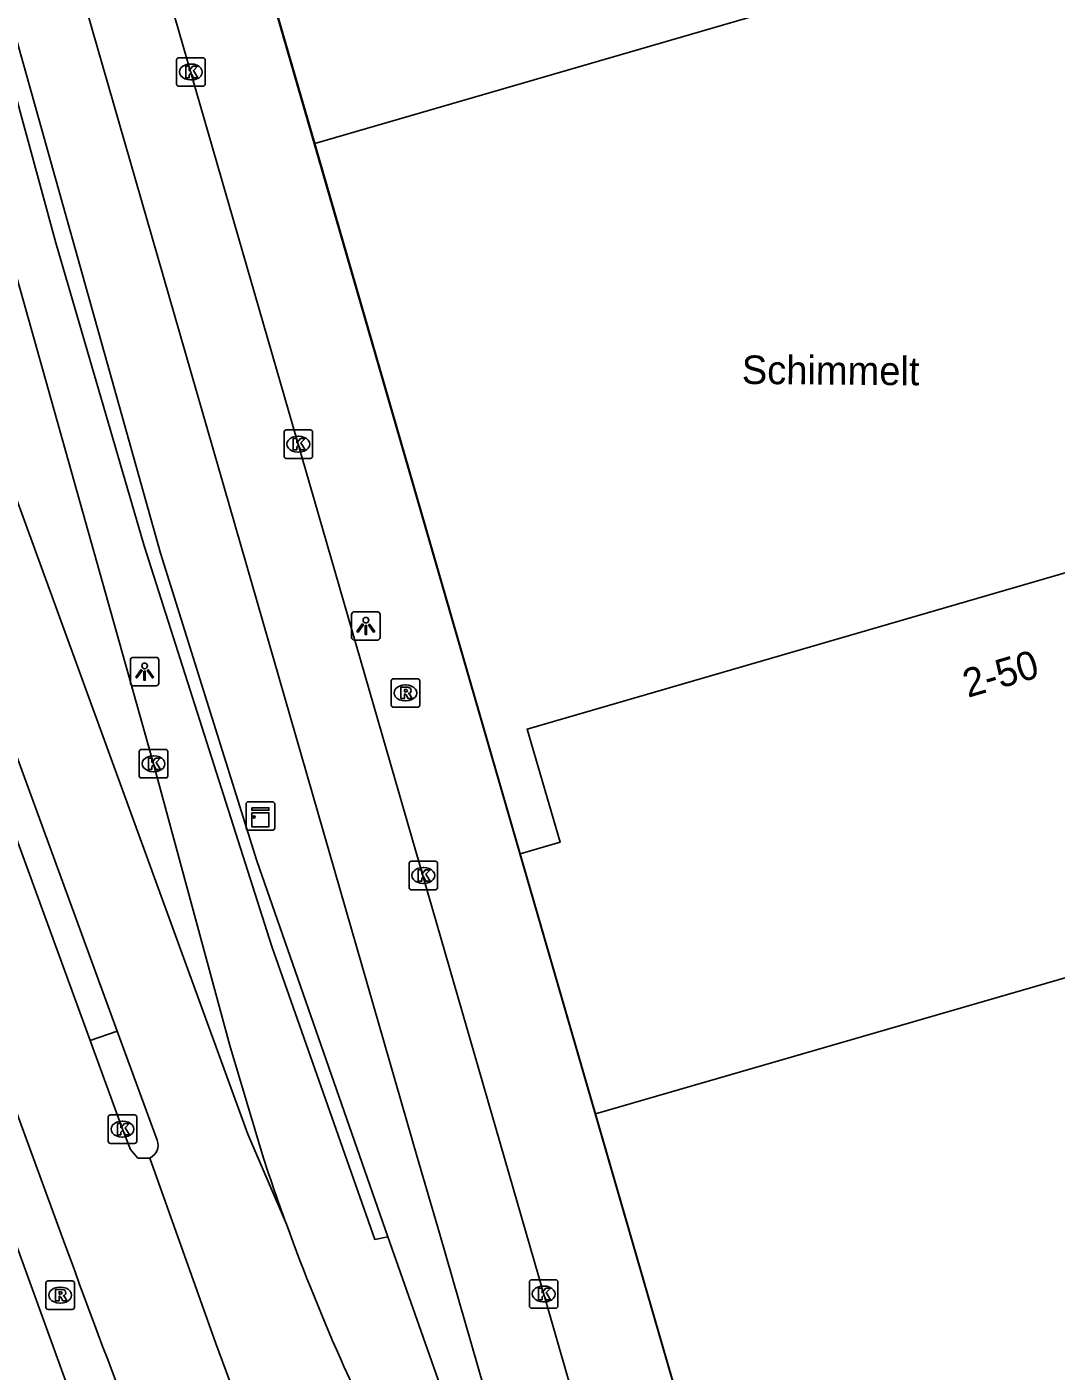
# Model space of a CAD drawing. Extents: x 160806 to 161707, y 383697 to 384148.
# Drawn here: x 161093.93 to 161130.08, y 383742.52 to 383789.72 of the extents above; entities that cross this region are included whole.
import ezdxf

# ---------------------------------------------------------------- set-up
doc = ezdxf.new("R2010")
doc.units = 0
for name, color, linetype in [('IMGEO_Fietspad_open', 7, 'Continuous'), ('IMGEO_Kast', 7, 'Continuous'), ('IMGEO_Kolk', 7, 'Continuous'), ('IMGEO_Lichtpunt', 7, 'Continuous'), ('IMGEO_Muur', 7, 'Continuous'), ('IMGEO_Openbare_ruimte_label', 7, 'Continuous'), ('IMGEO_OVBaan_gesloten', 7, 'Continuous'), ('IMGEO_Pand', 7, 'Continuous'), ('IMGEO_Pand_nummerreeks', 7, 'Continuous'), ('IMGEO_Pand_overbouw', 7, 'Continuous'), ('IMGEO_Rijbaan_lokaal_gesloten', 7, 'Continuous'), ('IMGEO_Rioolput', 7, 'Continuous'), ('IMGEO_Verkeerseiland_open', 7, 'Continuous'), ('IMGEO_Voetpad_open', 7, 'Continuous')]:
    doc.layers.add(name, color=color, linetype=linetype)

msp = doc.modelspace()

# ---------------------------------------------------------------- linework, layer by layer
at = {"layer": 'IMGEO_Fietspad_open'}
for points in [[(161122.975, 383708.589), (161122.859, 383708.842), (161122.656, 383709.073), (161122.247, 383709.896), (161112.327, 383744.363), (161110.707, 383750), (161094.816, 383804.968)], [(161092.305, 383803.171), (161107.65, 383750), (161108.414, 383747.365), (161112.465, 383733.297)]]:
    msp.add_lwpolyline(points, dxfattribs=at)
at = {"layer": 'IMGEO_Kast'}
for p, q in [((161101.63, 383761.583), (161101.63, 383762.424)), ((161101.63, 383762.424), (161101.63, 383761.583)), ((161101.705, 383762.508), (161102.546, 383762.508)), ((161102.546, 383762.508), (161101.705, 383762.508)), ((161102.63, 383762.433), (161102.63, 383761.592)), ((161102.63, 383761.592), (161102.63, 383762.433)), ((161102.555, 383761.508), (161101.714, 383761.508)), ((161101.714, 383761.508), (161102.555, 383761.508))]:
    msp.add_line(p, q, dxfattribs=at)
for points in [[(161101.825, 383762.298), (161102.425, 383762.298), (161102.425, 383762.213), (161101.825, 383762.213), (161101.825, 383762.298)], [(161101.825, 383762.123), (161102.425, 383762.123), (161102.425, 383761.634), (161101.825, 383761.634), (161101.825, 383762.123)]]:
    msp.add_lwpolyline(points, dxfattribs=at)
msp.add_circle((161101.909, 383761.972), 0.0377, dxfattribs=at)
for centre, start, end in [((161101.708, 383762.43), 92.4484, 184.2845), ((161101.708, 383762.43), 92.4484, 184.2845), ((161102.552, 383762.43), 2.4484, 94.2845), ((161102.552, 383762.43), 2.4484, 94.2845), ((161101.708, 383761.586), 182.4484, 274.2845), ((161101.708, 383761.586), 182.4484, 274.2845), ((161102.552, 383761.586), 272.4484, 4.2845), ((161102.552, 383761.586), 272.4484, 4.2845)]:
    msp.add_arc(centre, 0.0779, start, end, dxfattribs=at)
at = {"layer": 'IMGEO_Kolk'}
for p, q in [((161099.186, 383787.707), (161099.186, 383788.559)), ((161099.261, 383788.633), (161100.113, 383788.633)), ((161100.187, 383788.559), (161100.187, 383787.707)), ((161099.674, 383788.413), (161099.699, 383788.413)), ((161100.113, 383787.633), (161099.261, 383787.633)), ((161099.697, 383787.853), (161099.672, 383787.853)), ((161102.959, 383774.637), (161102.959, 383775.489)), ((161103.034, 383775.563), (161103.886, 383775.563)), ((161103.447, 383775.343), (161103.472, 383775.343)), ((161103.96, 383775.489), (161103.96, 383774.637)), ((161103.47, 383774.783), (161103.445, 383774.783)), ((161103.886, 383774.563), (161103.034, 383774.563)), ((161097.874, 383763.418), (161097.874, 383764.27)), ((161097.949, 383764.344), (161098.801, 383764.344)), ((161098.362, 383764.124), (161098.387, 383764.124)), ((161098.875, 383764.27), (161098.875, 383763.418)), ((161098.385, 383763.564), (161098.36, 383763.564)), ((161098.801, 383763.344), (161097.949, 383763.344)), ((161107.351, 383759.496), (161107.351, 383760.348)), ((161107.426, 383760.422), (161108.278, 383760.422)), ((161107.839, 383760.202), (161107.864, 383760.202)), ((161108.352, 383760.348), (161108.352, 383759.496)), ((161108.278, 383759.422), (161107.426, 383759.422)), ((161107.862, 383759.642), (161107.837, 383759.642)), ((161096.783, 383750.588), (161096.783, 383751.44)), ((161096.858, 383751.514), (161097.71, 383751.514)), ((161097.271, 383751.294), (161097.296, 383751.294)), ((161097.784, 383751.44), (161097.784, 383750.588)), ((161097.294, 383750.734), (161097.269, 383750.734)), ((161097.71, 383750.514), (161096.858, 383750.514)), ((161111.578, 383744.799), (161111.578, 383745.651)), ((161111.653, 383745.725), (161112.505, 383745.725)), ((161112.579, 383745.651), (161112.579, 383744.799)), ((161112.066, 383745.505), (161112.091, 383745.505)), ((161112.505, 383744.725), (161111.653, 383744.725)), ((161112.089, 383744.945), (161112.064, 383744.945))]:
    msp.add_line(p, q, dxfattribs=at)
for points in [[(161099.186, 383787.707), (161099.186, 383788.559)], [(161099.261, 383788.633), (161100.113, 383788.633)], [(161100.187, 383788.559), (161100.187, 383787.707)], [(161099.507, 383788.333), (161099.63, 383788.333), (161099.63, 383788.182), (161099.76, 383788.333), (161099.924, 383788.333), (161099.778, 383788.182), (161099.931, 383787.933), (161099.779, 383787.933), (161099.694, 383788.097), (161099.63, 383788.03), (161099.63, 383787.933), (161099.507, 383787.933), (161099.507, 383788.333)], [(161100.113, 383787.633), (161099.261, 383787.633)], [(161102.959, 383774.637), (161102.959, 383775.489)], [(161103.034, 383775.563), (161103.886, 383775.563)], [(161103.28, 383775.263), (161103.403, 383775.263), (161103.403, 383775.112), (161103.533, 383775.263), (161103.697, 383775.263), (161103.551, 383775.112), (161103.704, 383774.863), (161103.552, 383774.863), (161103.467, 383775.027), (161103.403, 383774.96), (161103.403, 383774.863), (161103.28, 383774.863), (161103.28, 383775.263)], [(161103.96, 383775.489), (161103.96, 383774.637)], [(161103.886, 383774.563), (161103.034, 383774.563)], [(161097.874, 383763.418), (161097.874, 383764.27)], [(161097.949, 383764.344), (161098.801, 383764.344)], [(161098.195, 383764.044), (161098.318, 383764.044), (161098.318, 383763.893), (161098.448, 383764.044), (161098.612, 383764.044), (161098.466, 383763.893), (161098.619, 383763.644), (161098.467, 383763.644), (161098.382, 383763.808), (161098.318, 383763.741), (161098.318, 383763.644), (161098.195, 383763.644), (161098.195, 383764.044)], [(161098.875, 383764.27), (161098.875, 383763.418)], [(161098.801, 383763.344), (161097.949, 383763.344)], [(161107.351, 383759.496), (161107.351, 383760.348)], [(161107.426, 383760.422), (161108.278, 383760.422)], [(161108.352, 383760.348), (161108.352, 383759.496)], [(161107.672, 383760.122), (161107.795, 383760.122), (161107.795, 383759.971), (161107.925, 383760.122), (161108.089, 383760.122), (161107.943, 383759.971), (161108.096, 383759.722), (161107.944, 383759.722), (161107.859, 383759.886), (161107.795, 383759.819), (161107.795, 383759.722), (161107.672, 383759.722), (161107.672, 383760.122)], [(161108.278, 383759.422), (161107.426, 383759.422)], [(161096.783, 383750.588), (161096.783, 383751.44)], [(161096.858, 383751.514), (161097.71, 383751.514)], [(161097.104, 383751.214), (161097.227, 383751.214), (161097.227, 383751.063), (161097.357, 383751.214), (161097.521, 383751.214), (161097.375, 383751.063), (161097.528, 383750.814), (161097.376, 383750.814), (161097.291, 383750.978), (161097.227, 383750.911), (161097.227, 383750.814), (161097.104, 383750.814), (161097.104, 383751.214)], [(161097.784, 383751.44), (161097.784, 383750.588)], [(161097.71, 383750.514), (161096.858, 383750.514)], [(161111.578, 383744.799), (161111.578, 383745.651)], [(161111.653, 383745.725), (161112.505, 383745.725)], [(161112.579, 383745.651), (161112.579, 383744.799)], [(161111.899, 383745.425), (161112.022, 383745.425), (161112.022, 383745.274), (161112.152, 383745.425), (161112.316, 383745.425), (161112.17, 383745.274), (161112.323, 383745.025), (161112.171, 383745.025), (161112.086, 383745.189), (161112.022, 383745.122), (161112.022, 383745.025), (161111.899, 383745.025), (161111.899, 383745.425)], [(161112.505, 383744.725), (161111.653, 383744.725)]]:
    msp.add_lwpolyline(points, dxfattribs=at)
for centre, start, end in [((161099.263, 383788.557), 91.552, 178.448), ((161099.263, 383788.557), 91.552, 178.448), ((161100.111, 383788.557), 1.552, 88.448), ((161100.111, 383788.557), 1.552, 88.448), ((161099.263, 383787.709), 181.552, 268.448), ((161099.263, 383787.709), 181.552, 268.448), ((161100.111, 383787.709), 271.552, 358.448), ((161100.111, 383787.709), 271.552, 358.448), ((161103.036, 383775.487), 91.552, 178.448), ((161103.036, 383775.487), 91.552, 178.448), ((161103.884, 383775.487), 1.552, 88.448), ((161103.884, 383775.487), 1.552, 88.448), ((161103.036, 383774.639), 181.552, 268.448), ((161103.036, 383774.639), 181.552, 268.448), ((161103.884, 383774.639), 271.552, 358.448), ((161103.884, 383774.639), 271.552, 358.448), ((161097.951, 383764.268), 91.552, 178.448), ((161097.951, 383764.268), 91.552, 178.448), ((161098.799, 383764.268), 1.552, 88.448), ((161098.799, 383764.268), 1.552, 88.448), ((161097.951, 383763.42), 181.552, 268.448), ((161097.951, 383763.42), 181.552, 268.448), ((161098.799, 383763.42), 271.552, 358.448), ((161098.799, 383763.42), 271.552, 358.448), ((161107.428, 383760.346), 91.552, 178.448), ((161107.428, 383760.346), 91.552, 178.448), ((161108.276, 383760.346), 1.552, 88.448), ((161108.276, 383760.346), 1.552, 88.448), ((161107.428, 383759.498), 181.552, 268.448), ((161107.428, 383759.498), 181.552, 268.448), ((161108.276, 383759.498), 271.552, 358.448), ((161108.276, 383759.498), 271.552, 358.448), ((161096.86, 383751.438), 91.552, 178.448), ((161096.86, 383751.438), 91.552, 178.448), ((161097.708, 383751.438), 1.552, 88.448), ((161097.708, 383751.438), 1.552, 88.448), ((161096.86, 383750.59), 181.552, 268.448), ((161096.86, 383750.59), 181.552, 268.448), ((161097.708, 383750.59), 271.552, 358.448), ((161097.708, 383750.59), 271.552, 358.448), ((161111.655, 383745.649), 91.552, 178.448), ((161111.655, 383745.649), 91.552, 178.448), ((161112.503, 383745.649), 1.552, 88.448), ((161112.503, 383745.649), 1.552, 88.448), ((161111.655, 383744.801), 181.552, 268.448), ((161111.655, 383744.801), 181.552, 268.448), ((161112.503, 383744.801), 271.552, 358.448), ((161112.503, 383744.801), 271.552, 358.448)]:
    msp.add_arc(centre, 0.0765, start, end, dxfattribs=at)
for centre, major_axis, ratio, start_param, end_param in [((161099.673, 383788.133), (-0.387, 0.002), 0.722429, 4.712389, 7.853982), ((161099.698, 383788.133), (-0.39, 0.002), 0.717154, 1.570796, 4.712389), ((161103.446, 383775.063), (-0.387, 0.002), 0.722429, 4.712389, 7.853982), ((161103.471, 383775.063), (-0.39, 0.002), 0.717154, 1.570796, 4.712389), ((161098.361, 383763.844), (-0.387, 0.002), 0.722429, 4.712389, 7.853982), ((161098.386, 383763.844), (-0.39, 0.002), 0.717154, 1.570796, 4.712389), ((161107.838, 383759.922), (-0.387, 0.002), 0.722429, 4.712389, 7.853982), ((161107.863, 383759.922), (-0.39, 0.002), 0.717154, 1.570796, 4.712389), ((161097.27, 383751.014), (-0.387, 0.002), 0.722429, 4.712389, 7.853982), ((161097.295, 383751.014), (-0.39, 0.002), 0.717154, 1.570796, 4.712389), ((161112.065, 383745.225), (-0.387, 0.002), 0.722429, 4.712389, 7.853982), ((161112.09, 383745.225), (-0.39, 0.002), 0.717154, 1.570796, 4.712389)]:
    msp.add_ellipse(centre, major_axis=major_axis, ratio=ratio, start_param=start_param, end_param=end_param, dxfattribs=at)
at = {"layer": 'IMGEO_Lichtpunt'}
for p, q in [((161106.236, 383769.182), (161105.428, 383769.182)), ((161106.236, 383769.182), (161105.428, 383769.182)), ((161105.334, 383769.087), (161105.334, 383768.28)), ((161105.334, 383769.087), (161105.334, 383768.28)), ((161106.33, 383768.28), (161106.33, 383769.087)), ((161106.33, 383768.28), (161106.33, 383769.087)), ((161105.428, 383768.186), (161106.236, 383768.186)), ((161105.428, 383768.186), (161106.236, 383768.186)), ((161097.563, 383767.483), (161097.563, 383766.676)), ((161097.563, 383767.483), (161097.563, 383766.676)), ((161098.465, 383767.578), (161097.657, 383767.578)), ((161098.465, 383767.578), (161097.657, 383767.578)), ((161098.559, 383766.676), (161098.559, 383767.483)), ((161098.559, 383766.676), (161098.559, 383767.483)), ((161097.657, 383766.582), (161098.465, 383766.582)), ((161097.657, 383766.582), (161098.465, 383766.582))]:
    msp.add_line(p, q, dxfattribs=at)
for points in [[(161105.708, 383768.751), (161105.747, 383768.723), (161105.559, 383768.461), (161105.521, 383768.488), (161105.708, 383768.751)], [(161105.81, 383768.703), (161105.857, 383768.703), (161105.857, 383768.381), (161105.81, 383768.381), (161105.81, 383768.703)], [(161105.92, 383768.723), (161105.958, 383768.75), (161106.145, 383768.488), (161106.106, 383768.46), (161105.92, 383768.723)], [(161097.937, 383767.147), (161097.976, 383767.119), (161097.788, 383766.857), (161097.75, 383766.884), (161097.937, 383767.147)], [(161098.039, 383767.099), (161098.086, 383767.099), (161098.086, 383766.777), (161098.039, 383766.777), (161098.039, 383767.099)], [(161098.149, 383767.119), (161098.187, 383767.146), (161098.374, 383766.884), (161098.335, 383766.856), (161098.149, 383767.119)]]:
    msp.add_lwpolyline(points, dxfattribs=at)
for centre in [(161105.833, 383768.885), (161098.062, 383767.281)]:
    msp.add_circle(centre, 0.0994, dxfattribs=at)
for centre, start, end in [((161105.428, 383769.087), 90, 180), ((161105.428, 383769.087), 90, 180), ((161106.236, 383769.087), 0, 90), ((161106.236, 383769.087), 0, 90), ((161105.428, 383768.28), 180, 270), ((161105.428, 383768.28), 180, 270), ((161106.236, 383768.28), 270, 0), ((161106.236, 383768.28), 270, 360), ((161097.657, 383767.483), 90, 180), ((161097.657, 383767.483), 90, 180), ((161098.465, 383767.483), 0, 90), ((161098.465, 383767.483), 0, 90), ((161097.657, 383766.676), 180, 270), ((161097.657, 383766.676), 180, 270), ((161098.465, 383766.676), 270, 0), ((161098.465, 383766.676), 270, 360)]:
    msp.add_arc(centre, 0.0946, start, end, dxfattribs=at)
at = {"layer": 'IMGEO_Muur'}
for points in [[(161106.609, 383747.23), (161106.142, 383747.144), (161102.53, 383757.429), (161098.042, 383771.49), (161094.945, 383782.134), (161091.88, 383793.365)], [(161092.373, 383793.515), (161098.622, 383771.238), (161102.008, 383760.438), (161106.609, 383747.23)], [(161104.037, 383785.627), (161111.258, 383760.68)], [(161113.902, 383751.548), (161121.123, 383726.602)]]:
    msp.add_lwpolyline(points, dxfattribs=at)
at = {"layer": 'IMGEO_OVBaan_gesloten'}
for points in [[(161102.235, 383750), (161101.051, 383753.951), (161098.374, 383763.844), (161092.283, 383785.463), (161090.16, 383792.842)], [(161103.041, 383747.674), (161101.686, 383750.837), (161094.204, 383771.373), (161086.746, 383791.803)], [(161083.782, 383790.902), (161086.058, 383784.64), (161097.094, 383754.459)], [(161096.146, 383754.129), (161082.829, 383790.612)], [(161095.134, 383747.328), (161080.062, 383788.476)], [(161098.248, 383750), (161097.827, 383750), (161097.566, 383750.295), (161097.284, 383751.013), (161096.146, 383754.129)], [(161097.094, 383754.459), (161098.503, 383750.621)], [(161098.248, 383750), (161100.564, 383743.492), (161107.332, 383725.232), (161114.19, 383707.765)]]:
    msp.add_lwpolyline(points, dxfattribs=at)
for centre, radius, start, end in [((161098.036, 383750.45), 0.498, 295.2525, 20.0986), ((161178.084, 383774.98), 79.857, 198.22896, 199.99525), ((161176.599, 383774.523), 78.305, 200.05218, 204.01794), ((161397.351, 383856.727), 321.408, 199.89967, 202.57883), ((161205.033, 383787.994), 109.762, 204.39986, 208.05722)]:
    msp.add_arc(centre, radius, start, end, dxfattribs=at)
at = {"layer": 'IMGEO_Pand'}
for points in [[(161098.648, 383804.243), (161104.037, 383785.627)], [(161104.037, 383785.627), (161138.655, 383795.672)], [(161144.737, 383774.709), (161111.5, 383765.061), (161112.655, 383761.086), (161111.258, 383760.68)], [(161113.902, 383751.548), (161148.546, 383761.579)], [(161111.258, 383760.68), (161113.902, 383751.548)]]:
    msp.add_lwpolyline(points, dxfattribs=at)
at = {"layer": 'IMGEO_Pand_overbouw'}
msp.add_lwpolyline([(161244.397, 383752.352), (161218.72, 383841.978), (161097.833, 383806.973), (161123.797, 383717.365)], close=True, dxfattribs=at)
at = {"layer": 'IMGEO_Rijbaan_lokaal_gesloten'}
msp.add_lwpolyline([(161094.759, 383743.637), (161080.521, 383782.879), (161078.277, 383787.537), (161077.524, 383788.998)], dxfattribs=at)
msp.add_arc((161607.188, 383928.487), 544.751, 199.83606, 202.25684, dxfattribs=at)
at = {"layer": 'IMGEO_Rioolput'}
for p, q in [((161106.799, 383766.829), (161107.651, 383766.829)), ((161106.724, 383765.903), (161106.724, 383766.755)), ((161107.212, 383766.609), (161107.237, 383766.609)), ((161107.725, 383766.755), (161107.725, 383765.903)), ((161107.651, 383765.829), (161106.799, 383765.829)), ((161107.235, 383766.049), (161107.21, 383766.049)), ((161094.595, 383744.76), (161094.595, 383745.612)), ((161094.67, 383745.686), (161095.522, 383745.686)), ((161095.596, 383745.612), (161095.596, 383744.76)), ((161095.083, 383745.466), (161095.108, 383745.466)), ((161095.522, 383744.686), (161094.67, 383744.686)), ((161095.106, 383744.906), (161095.081, 383744.906))]:
    msp.add_line(p, q, dxfattribs=at)
for points in [[(161106.799, 383766.829), (161107.651, 383766.829)], [(161106.724, 383765.903), (161106.724, 383766.755)], [(161107.313, 383766.527), (161107.061, 383766.529), (161107.061, 383766.129)], [(161107.061, 383766.129), (161107.185, 383766.129), (161107.185, 383766.291), (161107.196, 383766.291)], [(161107.239, 383766.448), (161107.185, 383766.448), (161107.185, 383766.367)], [(161107.185, 383766.367), (161107.237, 383766.367)], [(161107.725, 383766.755), (161107.725, 383765.903)], [(161107.651, 383765.829), (161106.799, 383765.829)], [(161107.243, 383766.262), (161107.314, 383766.129), (161107.454, 383766.129), (161107.389, 383766.255)], [(161094.595, 383744.76), (161094.595, 383745.612)], [(161094.67, 383745.686), (161095.522, 383745.686)], [(161095.596, 383745.612), (161095.596, 383744.76)], [(161095.184, 383745.384), (161094.932, 383745.386), (161094.932, 383744.986)], [(161094.932, 383744.986), (161095.056, 383744.986), (161095.056, 383745.148), (161095.067, 383745.148)], [(161095.11, 383745.305), (161095.056, 383745.305), (161095.056, 383745.224)], [(161095.056, 383745.224), (161095.108, 383745.224)], [(161095.114, 383745.119), (161095.185, 383744.986), (161095.325, 383744.986), (161095.26, 383745.112)], [(161095.522, 383744.686), (161094.67, 383744.686)]]:
    msp.add_lwpolyline(points, dxfattribs=at)
for centre, radius, start, end in [((161106.801, 383766.753), 0.0765, 91.552, 178.448), ((161106.801, 383766.753), 0.0765, 91.552, 178.448), ((161107.649, 383766.753), 0.0765, 1.552, 88.448), ((161107.649, 383766.753), 0.0765, 1.552, 88.448), ((161107.195, 383766.238), 0.0533, 26.0293, 88.6989), ((161107.221, 383766.556), 0.19, 274.7715, 282.9687), ((161107.245, 383766.352), 0.0964, 77.0061, 93.1865), ((161107.259, 383766.409), 0.0378, 276.6634, 79.6772), ((161107.312, 383766.417), 0.109, 350.3612, 89.416), ((161107.31, 383766.417), 0.112, 277.5842, 350.9817), ((161107.294, 383766.202), 0.108, 29.5134, 73.7905), ((161106.801, 383765.905), 0.0765, 181.552, 268.448), ((161106.801, 383765.905), 0.0765, 181.552, 268.448), ((161107.649, 383765.905), 0.0765, 271.552, 358.448), ((161107.649, 383765.905), 0.0765, 271.552, 358.448), ((161094.672, 383745.61), 0.0765, 91.552, 178.448), ((161094.672, 383745.61), 0.0765, 91.552, 178.448), ((161095.52, 383745.61), 0.0765, 1.552, 88.448), ((161095.52, 383745.61), 0.0765, 1.552, 88.448), ((161095.066, 383745.095), 0.0533, 26.0293, 88.6989), ((161095.092, 383745.413), 0.19, 274.7715, 282.9687), ((161095.116, 383745.209), 0.0964, 77.0061, 93.1865), ((161095.13, 383745.266), 0.0378, 276.6634, 79.6772), ((161095.183, 383745.274), 0.109, 350.3612, 89.416), ((161095.181, 383745.274), 0.112, 277.5842, 350.9817), ((161095.165, 383745.059), 0.108, 29.5134, 73.7905), ((161094.672, 383744.762), 0.0765, 181.552, 268.448), ((161094.672, 383744.762), 0.0765, 181.552, 268.448), ((161095.52, 383744.762), 0.0765, 271.552, 358.448), ((161095.52, 383744.762), 0.0765, 271.552, 358.448)]:
    msp.add_arc(centre, radius, start, end, dxfattribs=at)
for centre, major_axis, ratio, start_param, end_param in [((161107.211, 383766.329), (-0.387, 0.002), 0.722429, 4.712389, 7.853982), ((161107.236, 383766.329), (-0.39, 0.002), 0.717154, 1.570796, 4.712389), ((161095.082, 383745.186), (-0.387, 0.002), 0.722429, 4.712389, 7.853982), ((161095.107, 383745.186), (-0.39, 0.002), 0.717154, 1.570796, 4.712389)]:
    msp.add_ellipse(centre, major_axis=major_axis, ratio=ratio, start_param=start_param, end_param=end_param, dxfattribs=at)
at = {"layer": 'IMGEO_Verkeerseiland_open'}
msp.add_lwpolyline([(161096.146, 383754.129), (161097.094, 383754.459)], dxfattribs=at)
at = {"layer": 'IMGEO_Voetpad_open'}
for points in [[(161111.258, 383760.68), (161104.037, 383785.627)], [(161121.123, 383726.602), (161113.902, 383751.548)], [(161106.609, 383747.23), (161111.592, 383733.071)]]:
    msp.add_lwpolyline(points, dxfattribs=at)

# ---------------------------------------------------------------- texts
at = {"layer": 'IMGEO_Openbare_ruimte_label'}
msp.add_text('Schimmelt', height=1, rotation=359.5416, dxfattribs=at).set_placement((161119.034, 383777.181))
at = {"layer": 'IMGEO_Pand_nummerreeks'}
msp.add_text('2-50', height=1, rotation=16.1966, dxfattribs=at).set_placement((161126.977, 383766.155))

doc.saveas('drawing.dxf')
